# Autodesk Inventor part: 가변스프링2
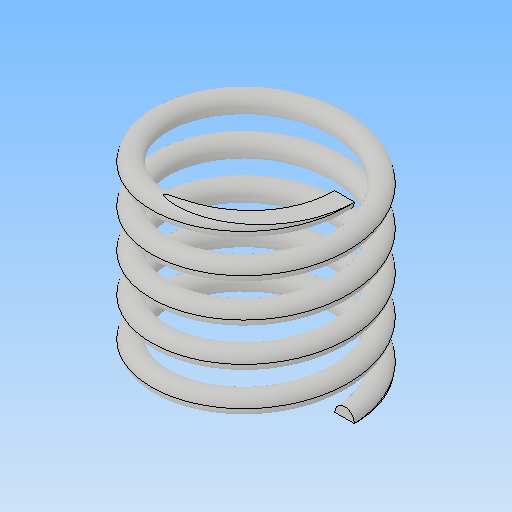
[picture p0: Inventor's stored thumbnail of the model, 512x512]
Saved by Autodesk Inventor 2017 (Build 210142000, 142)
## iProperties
Part Number: 가변스프링2
Material: 일반
Document SubType Name: Modeling
Designer: MRC
Density: 1 g/cm^3
Appearance: 기본값
Mass: 0.870346 g
Surface Area: 17.6923 cm^2
Volume: 0.870346 cm^3
Author: MRC
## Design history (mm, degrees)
sketch "스케치1"
  geometry: L1 (0, 0)-(0, 19.5); L2 (0, 0)-(9, 0); L3 (0, 19.5)-(9, 19.5); C1 r 1 at (9, 0)
  constraints: 6 end point, 2 horizontal, 1 centre point, 1 coincident, 1 vertical
  dimensions: "d0" = 19.5 distance of L1.start L1.end (derived); "d1" = 9 distance of L1.start L2.end; "d2" = 9 distance of L1.end L3.end; "d3" = 2 diameter of C1
feature "코일1" sketch "스케치1" pitch "d4" = 10; turns "d6" = 5; dims "d5" = 19.5 (= d0), "d7" = 0, angle "d8" = 90 deg, angle "d9" = 90 deg, "d10" = 0, "d11" = 0
sketch "스케치2"
  geometry: L1 (19.5, 16.059)-(0, 16.059); L2 (0, 16.059)-(0, -16.059); L3 (0, -16.059)-(19.5, -16.059); L4 (19.5, -16.059)-(19.5, 16.059); 2 further points
  constraints: 8 end point, 2 parallel, 1 coincident, 1 horizontal, 1 midpoint, 1 perpendicular
  dimensions: "d12" = 19.5 distance of L2.end L3.end (= d0); "d13" = 32.11845 distance of L3.end L1.start
extrude "돌출1" sketch "스케치2" stored distance "d14" = 0; taper "d15" = 0 deg
node "솔리드1"
